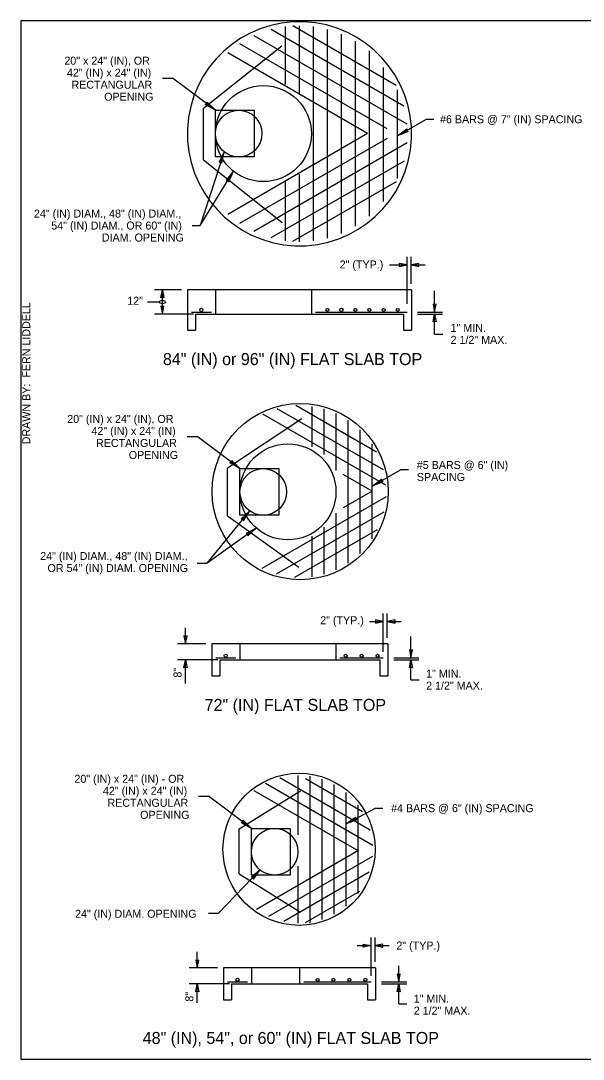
# Model space of a CAD drawing. Extents: x 99862 to 103151, y 100000 to 102076.
# Drawn here: x 99862 to 100987, y 100000 to 102076 of the extents above; entities that cross this region are included whole.
import ezdxf

# ---------------------------------------------------------------- set-up
doc = ezdxf.new("R2010")
doc.units = 0
for name, color, linetype in [('Level 1', 7, 'Continuous'), ('Level 15', 7, 'Continuous'), ('Level 17', 7, 'Continuous'), ('Level 18', 7, 'Continuous'), ('Level 20', 7, 'Continuous'), ('Level 60', 7, 'Continuous'), ('Level 62', 7, 'Continuous')]:
    doc.layers.add(name, color=color, linetype=linetype)

msp = doc.modelspace()

# ---------------------------------------------------------------- linework, layer by layer
at = {"layer": 'Level 1'}
msp.add_lwpolyline([(99862, 99999.5), (103151, 99999.5), (103151, 102075.5), (99862, 102075.5)], close=True, dxfattribs=at)
for points in [[(100251.2, 101803.3), (100251.2, 101896.5), (100328.9, 101896.5), (100328.9, 101803.3), (100251.2, 101803.3)], [(100300.3, 101087.1), (100300.3, 101180.3), (100378, 101180.3), (100378, 101087.1), (100300.3, 101087.1)], [(100323.2, 100367.7), (100323.2, 100460.9), (100400.8, 100460.9), (100400.8, 100367.7), (100323.2, 100367.7)]]:
    msp.add_lwpolyline(points, dxfattribs=at)
for centre in [(100297.8, 101849.9), (100346.9, 101133.7)]:
    msp.add_circle(centre, 46.6, dxfattribs=at)
at = {"layer": 'Level 15'}
for p, q in [((100145.5, 101960.9), (100165.5, 101960.9)), ((100251.2, 101896.5), (100165.5, 101960.9)), ((100615.5, 101845.4), (100671.8, 101877.9)), ((100687.8, 101877.9), (100671.8, 101877.9)), ((100268.6, 101813.5), (100220.9, 101666.1)), ((100220.9, 101666.1), (100287.5, 101774.7)), ((100204.6, 101666.1), (100220.9, 101666.1)), ((100634.5, 101509.4), (100634.5, 101603.3)), ((100642.5, 101549.3), (100642.5, 101603.3)), ((100599.2, 101587.3), (100634.5, 101587.3)), ((100642.5, 101587.3), (100670.6, 101587.3)), ((100183.2, 101537.3), (100129.3, 101537.3)), ((100145.2, 101489.2), (100145.2, 101537.3)), ((100689.7, 101493.2), (100689.7, 101535.7)), ((100139.2, 101513.2), (100115.2, 101513.2)), ((100207.3, 101489.2), (100129.3, 101489.2)), ((100655.2, 101493.2), (100705.7, 101493.2)), ((100655.2, 101489.2), (100705.7, 101489.2)), ((100689.7, 101449.3), (100689.7, 101489.2)), ((100689.7, 101449.3), (100705.9, 101449.3)), ((100194.7, 101244.7), (100214.6, 101244.7)), ((100300.3, 101180.3), (100214.6, 101244.7)), ((100565.1, 101145.3), (100621.4, 101177.8)), ((100637.4, 101177.8), (100621.4, 101177.8)), ((100234.6, 100991.4), (100319.8, 101095.6)), ((100333.1, 101061.4), (100234.6, 100991.4)), ((100214.6, 100991.4), (100234.6, 100991.4)), ((100559.2, 100874.6), (100587.1, 100874.6)), ((100587.1, 100813.9), (100587.1, 100890.6)), ((100595.1, 100842), (100595.1, 100890.6)), ((100595.1, 100874.6), (100623.1, 100874.6)), ((100191.5, 100830), (100191.5, 100861.9)), ((100642.3, 100801.9), (100642.3, 100844.4)), ((100231.8, 100830), (100175.5, 100830)), ((100255.9, 100797.9), (100175.5, 100797.9)), ((100191.5, 100750.6), (100191.5, 100797.9)), ((100607.8, 100801.9), (100658.3, 100801.9)), ((100607.8, 100797.9), (100658.3, 100797.9)), ((100642.3, 100758), (100642.3, 100797.9)), ((100642.3, 100758), (100658.5, 100758)), ((100217.5, 100525.3), (100237.5, 100525.3)), ((100323.2, 100460.9), (100237.5, 100525.3)), ((100512.8, 100470), (100570, 100500.7)), ((100586, 100500.7), (100570, 100500.7)), ((100341.1, 100377.8), (100257.4, 100291.5)), ((100237.4, 100291.5), (100257.4, 100291.5)), ((100562.6, 100166), (100562.6, 100242.7)), ((100570.6, 100194.1), (100570.6, 100242.7)), ((100215.1, 100182.1), (100215.1, 100214)), ((100534.7, 100226.7), (100562.6, 100226.7)), ((100570.6, 100226.7), (100598.6, 100226.7)), ((100255.3, 100182.1), (100199.1, 100182.1)), ((100617.9, 100154), (100617.9, 100186)), ((100279.4, 100150), (100199.1, 100150)), ((100215.1, 100112.3), (100215.1, 100150)), ((100583.3, 100154), (100633.9, 100154)), ((100583.3, 100150), (100633.9, 100150)), ((100617.9, 100110.1), (100617.9, 100150)), ((100617.9, 100110.1), (100634, 100110.1))]:
    msp.add_line(p, q, dxfattribs=at)
for points in [[(100251.2, 101896.5), (100231.1, 101907.8), (100233.8, 101909.6), (100234.7, 101912.6)], [(100615.5, 101845.4), (100633.8, 101859.4), (100634.3, 101856.2), (100636.7, 101854.2)], [(100268.6, 101813.5), (100258.6, 101792.8), (100261.8, 101792.8), (100264.3, 101790.9)], [(100287.5, 101774.7), (100273, 101756.8), (100276.1, 101756.1), (100278.1, 101753.7)], [(100634.5, 101587.3), (100618.8, 101590.4), (100619.5, 101587.3), (100618.8, 101584.2)], [(100642.5, 101587.3), (100658.2, 101584.2), (100657.5, 101587.3), (100658.2, 101590.4)], [(100145.2, 101537.3), (100148.3, 101521.6), (100145.2, 101522.3), (100142.1, 101521.6)], [(100145.2, 101489.2), (100148.3, 101504.9), (100145.2, 101504.2), (100142.1, 101504.9)], [(100689.7, 101493.2), (100692.8, 101508.9), (100689.7, 101508.2), (100686.7, 101508.9)], [(100689.7, 101489.2), (100692.8, 101473.5), (100689.7, 101474.2), (100686.7, 101473.5)], [(100300.3, 101180.3), (100280.4, 101191.8), (100283, 101193.6), (100284, 101196.6)], [(100565.1, 101145.3), (100583.4, 101159.3), (100583.9, 101156.2), (100586.4, 101154.1)], [(100319.8, 101095.6), (100303, 101079.8), (100306, 101078.7), (100307.6, 101076)], [(100333.1, 101061.4), (100312.8, 101050.6), (100315.4, 101048.8), (100316.2, 101045.7)], [(100587.1, 100874.6), (100571.4, 100877.7), (100572.1, 100874.6), (100571.4, 100871.5)], [(100595.1, 100874.6), (100610.8, 100871.5), (100610.1, 100874.6), (100610.8, 100877.7)], [(100191.5, 100830), (100194.6, 100845.7), (100191.5, 100844.9), (100188.4, 100845.7)], [(100642.3, 100801.9), (100645.4, 100817.6), (100642.3, 100816.9), (100639.2, 100817.6)], [(100191.5, 100797.9), (100194.6, 100782.1), (100191.5, 100782.9), (100188.4, 100782.1)], [(100642.3, 100797.9), (100645.4, 100782.1), (100642.3, 100782.9), (100639.2, 100782.1)], [(100512.8, 100470), (100531.4, 100483.5), (100531.9, 100480.4), (100534.3, 100478.2)], [(100323.2, 100460.9), (100303.2, 100472.4), (100305.9, 100474.2), (100306.9, 100477.2)], [(100341.1, 100377.8), (100323.2, 100363.4), (100326.1, 100362.1), (100327.5, 100359.3)], [(100562.6, 100226.7), (100546.9, 100223.7), (100547.6, 100226.7), (100546.9, 100229.8)], [(100570.6, 100226.7), (100586.4, 100223.7), (100585.6, 100226.7), (100586.4, 100229.8)], [(100215.1, 100182.1), (100218.2, 100197.8), (100215.1, 100197.1), (100212, 100197.8)], [(100617.9, 100154), (100620.9, 100169.7), (100617.9, 100169), (100614.8, 100169.7)], [(100215.1, 100150), (100218.2, 100134.3), (100215.1, 100135), (100212, 100134.3)], [(100617.9, 100150), (100620.9, 100134.3), (100617.9, 100135), (100614.8, 100134.3)]]:
    msp.add_lwpolyline(points, close=True, dxfattribs=at)
msp.add_ellipse((100145.2, 101513.2), major_axis=(-6, 0), ratio=0.57735, dxfattribs=at)
at = {"layer": 'Level 17'}
for p, q in [((100643.2, 101537.3), (100195.2, 101537.3)), ((100195.2, 101537.3), (100195.2, 101457.2)), ((100251.2, 101537.3), (100251.2, 101489.2)), ((100443.2, 101537.3), (100443.2, 101489.2)), ((100643.2, 101537.3), (100643.2, 101457.2)), ((100211.2, 101489.2), (100627.2, 101489.2)), ((100211.2, 101489.2), (100211.2, 101457.2)), ((100627.2, 101489.2), (100627.2, 101457.2)), ((100195.2, 101457.2), (100211.2, 101457.2)), ((100627.2, 101457.2), (100643.2, 101457.2)), ((100595.8, 100830), (100243.8, 100830)), ((100243.8, 100830), (100243.8, 100765.9)), ((100299.8, 100830), (100299.8, 100797.9)), ((100491.8, 100830), (100491.8, 100797.9)), ((100595.8, 100830), (100595.8, 100765.9)), ((100259.8, 100797.9), (100579.8, 100797.9)), ((100259.8, 100797.9), (100259.8, 100765.9)), ((100579.8, 100797.9), (100579.8, 100765.9)), ((100243.8, 100765.9), (100259.8, 100765.9)), ((100579.8, 100765.9), (100595.8, 100765.9)), ((100571.3, 100182.1), (100267.3, 100182.1)), ((100267.3, 100182.1), (100267.3, 100118)), ((100323.3, 100182.1), (100323.3, 100150)), ((100419.3, 100182.1), (100419.3, 100150)), ((100571.3, 100182.1), (100571.3, 100118)), ((100283.3, 100150), (100555.3, 100150)), ((100283.3, 100150), (100283.3, 100118)), ((100555.3, 100150), (100555.3, 100118)), ((100267.3, 100118), (100283.3, 100118)), ((100555.3, 100118), (100571.3, 100118))]:
    msp.add_line(p, q, dxfattribs=at)
for centre, radius in [((100347.2, 101849.9), 96), ((100420.8, 101134.3), 176.1), ((100396.3, 101133.7), 96), ((100418.5, 100419.2), 152.1), ((100369.8, 100414.3), 46.6)]:
    msp.add_circle(centre, radius, dxfattribs=at)
msp.add_arc((100419.5, 101849.6), 224.1, 357.64, 357.5432, dxfattribs=at)
at = {"layer": 'Level 18'}
for p, q in [((100628.3, 101904.8), (100362.7, 102058)), ((100391.2, 101948), (100391.2, 102063.8)), ((100612.8, 101946.1), (100406.3, 102065.2)), ((100419.3, 101928.9), (100419.3, 102065.6)), ((100447.3, 101635.4), (100447.3, 102063.8)), ((100475.3, 101640.9), (100475.3, 102058.3)), ((100634.7, 101868.8), (100328.5, 102045.5)), ((100503.3, 101650.5), (100503.3, 102048.7)), ((100227.2, 101900.7), (100384, 102025.3)), ((100594.5, 101859.6), (100300.1, 102029.6)), ((100531.3, 101664.8), (100531.3, 102034.4)), ((100559.4, 101685), (100559.3, 102015.4)), ((100555.3, 101849.9), (100276, 102011.1)), ((100587.4, 101714.1), (100587.4, 101982.4)), ((100615.4, 101760.1), (100615.4, 101937.4)), ((100227.2, 101797.6), (100227.2, 101900.7)), ((100555.3, 101849.9), (100275.8, 101688.4)), ((100594.5, 101840.1), (100299.7, 101669.9)), ((100634.5, 101831.3), (100328.1, 101653.9)), ((100227.2, 101797.6), (100384.9, 101672.2)), ((100628.5, 101795), (100362.2, 101641.4)), ((100419.3, 101633.6), (100419.3, 101769.1)), ((100391.2, 101635.5), (100391.2, 101753.8)), ((100613.1, 101753.8), (100405.6, 101634.1)), ((100203.2, 101493.2), (100243.2, 101493.2)), ((100451.2, 101493.2), (100634.5, 101493.2)), ((100592.3, 101147), (100346, 101289.2)), ((100587.2, 101177.7), (100374.5, 101299.9)), ((100573.6, 101213.3), (100412.1, 101306.1)), ((100444.5, 101223.8), (100444.5, 101304.7)), ((100468.5, 101208.2), (100468.5, 101299.6)), ((100492.5, 101176.2), (100492.5, 101290.6)), ((100424, 101279.7), (100275.7, 101181)), ((100516.5, 100991.4), (100516.5, 101277.2)), ((100540.5, 101010.8), (100540.5, 101257.8)), ((100564.5, 101039.8), (100564.5, 101228.8)), ((100275.7, 101086.1), (100275.7, 101181)), ((100564.5, 101135.4), (100507.1, 101168.5)), ((100592.5, 101123.7), (100344.3, 100980.3)), ((100564.5, 101135.3), (100507, 101102.1)), ((100275.7, 101086.1), (100418, 100983)), ((100587.8, 101093.1), (100372.7, 100969.2)), ((100492.5, 100978), (100492.5, 101091.1)), ((100468.5, 100969.1), (100468.5, 101062.9)), ((100575, 101058.1), (100409.5, 100962.7)), ((100444.5, 100963.9), (100444.5, 101045.3)), ((100251.8, 100801.9), (100291.8, 100801.9)), ((100499.8, 100801.9), (100587.1, 100801.9)), ((100561.1, 100457.5), (100380.3, 100561.8)), ((100416.7, 100448.1), (100416.7, 100566.8)), ((100440.7, 100272.1), (100440.7, 100565.2)), ((100565.9, 100427), (100351.6, 100550.9)), ((100545.7, 100494.1), (100431.4, 100560.1)), ((100464.6, 100278.9), (100464.6, 100559.4)), ((100488.7, 100289.3), (100488.7, 100549)), ((100299, 100460), (100421.2, 100536.2)), ((100538, 100415.4), (100328.6, 100536.3)), ((100512.7, 100305.5), (100512.7, 100532.8)), ((100536.7, 100330.8), (100536.7, 100507.6)), ((100299, 100369.8), (100299, 100460)), ((100537.3, 100416.5), (100333.2, 100298.6)), ((100565.4, 100404.9), (100357.3, 100284.7)), ((100416.7, 100271.5), (100416.7, 100385.7)), ((100299, 100369.8), (100421.2, 100293.6)), ((100558.8, 100373.4), (100387.8, 100274.7)), ((100539.4, 100334.5), (100431.1, 100272.1)), ((100275.3, 100154), (100315.3, 100154)), ((100428.3, 100154), (100562.6, 100154))]:
    msp.add_line(p, q, dxfattribs=at)
for centre, radius in [((100223.2, 101497.5), 3.2), ((100475.3, 101497.5), 3.07), ((100503.3, 101497.5), 3.2), ((100531.3, 101497.5), 2.97), ((100559.3, 101497.5), 3), ((100587.7, 101497.5), 2.97), ((100616, 101497.5), 2.97), ((100271.8, 100806.3), 3.2), ((100511.9, 100806), 3), ((100543.8, 100806), 2.97), ((100575.5, 100806), 2.97), ((100295.4, 100158.5), 3.2), ((100455.5, 100158.2), 2.97), ((100487.4, 100158.4), 3), ((100519.3, 100158.4), 2.97), ((100551.1, 100158.4), 2.97)]:
    msp.add_circle(centre, radius, dxfattribs=at)
at = {"layer": 'Level 60'}
msp.add_line((99862, 99999.5), (99862, 99999.5), dxfattribs=at)

# ---------------------------------------------------------------- texts
at = {"layer": 'Level 20'}
for s, height, p in [('20" x 24" (IN), OR', 16, (99949.2, 101987.7)), ('42" (IN) x 24" (IN) ', 16, (99954.3, 101963.7)), ('RECTANGULAR', 16, (99963.4, 101939.7)), ('OPENING', 16, (100028.8, 101915.7)), ('#6 BARS @ 7" (IN) SPACING', 16, (100700.5, 101870.6)), ('24" (IN) DIAM., 48" (IN) DIAM.,', 16, (99888.4, 101682.1)), ('54" (IN) DIAM., OR 60" (IN)', 16, (99923, 101658.1)), (' DIAM. OPENING', 16, (100018.2, 101634.1)), ('2" (TYP.)', 16, (100499.8, 101580.3)), ('12"', 16, (100075, 101507.7)), ('1" MIN.', 16, (100721.6, 101453.6)), ('2 1/2" MAX.', 16, (100721.6, 101429.6)), ('84" (IN) or 96" (IN) FLAT SLAB TOP', 24, (100146.3, 101387.2)), ('20" (IN) x 24" (IN), OR', 16, (99954.9, 101271.5)), ('42" (IN) x 24" (IN) ', 16, (100003.4, 101247.5)), ('RECTANGULAR', 16, (100012.5, 101223.5)), ('OPENING', 16, (100078, 101199.5)), ('#5 BARS @ 6" (IN) ', 16, (100654.1, 101179.5)), ('SPACING', 16, (100654.1, 101155.5)), ('24" (IN) DIAM., 48" (IN) DIAM., ', 16, (99900.9, 100997.5)), ('OR 54" (IN) DIAM. OPENING', 16, (99915.5, 100973.5)), ('2" (TYP.)', 16, (100460.9, 100869)), ('1" MIN.', 16, (100672.7, 100762.4)), ('2 1/2" MAX.', 16, (100672.7, 100738.4)), ('72" (IN) FLAT SLAB TOP', 24, (100229.8, 100695.9)), ('20" (IN) x 24" (IN) - OR', 16, (99969.3, 100552.1)), ('42" (IN) x 24" (IN) ', 16, (100026.3, 100528.1)), ('RECTANGULAR', 16, (100035.4, 100504.1)), ('#4 BARS @ 6" (IN) SPACING', 16, (100602.7, 100493.4)), ('OPENING', 16, (100100.8, 100480.1)), ('24" (IN) DIAM. OPENING', 16, (99970.6, 100282.3)), ('2" (TYP.)', 16, (100613.2, 100218.8)), ('1" MIN.', 16, (100647.9, 100112.6)), ('2 1/2" MAX.', 16, (100647.9, 100088.6)), ('48" (IN), 54", or 60" (IN) FLAT SLAB TOP', 24, (100105.9, 100030))]:
    msp.add_text(s, height=height, dxfattribs=at).set_placement(p)
for p in [(100183.5, 100762.4), (100207.1, 100114.6)]:
    msp.add_text('8"', height=16, rotation=90, dxfattribs=at).set_placement(p)
at = {"layer": 'Level 62'}
msp.add_text('DRAWN BY:  FERN LIDDELL', height=16, rotation=90, dxfattribs=at).set_placement((99881, 101228.8))

doc.saveas('drawing.dxf')
